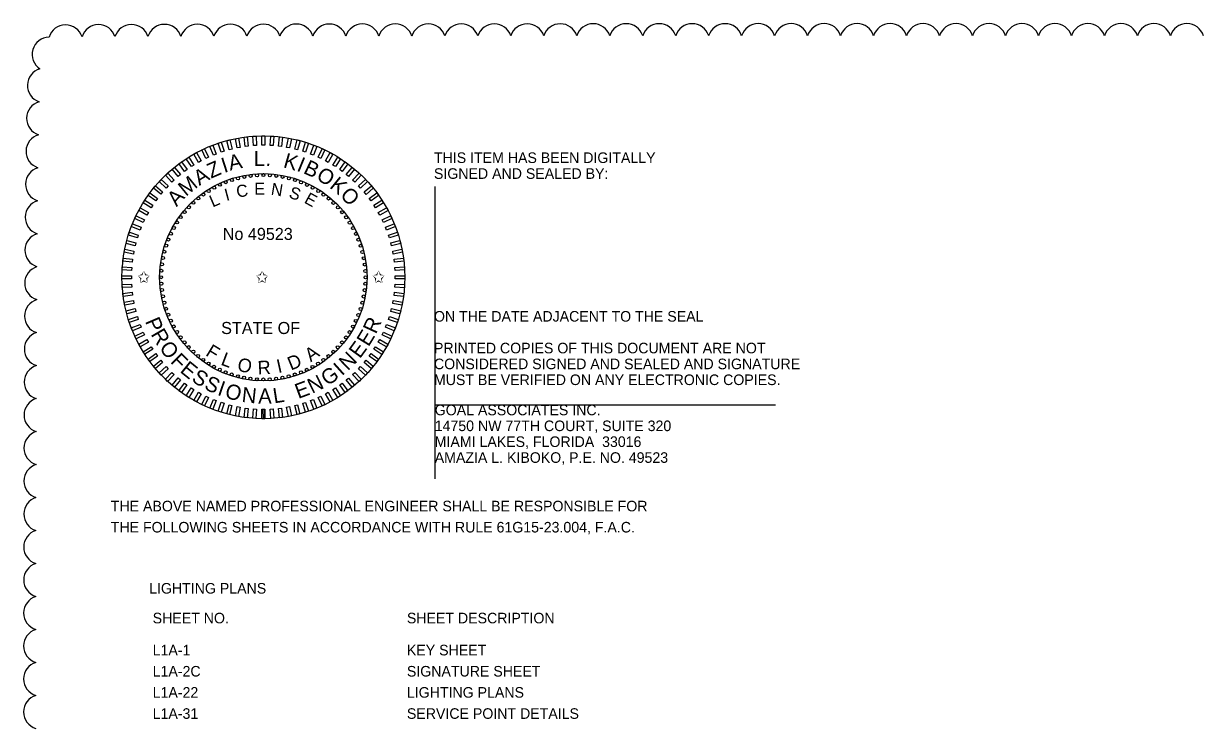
# Model space of a CAD drawing. Extents: x -811.2 to -795.1, y -2238.2 to -2204.
# Drawn here: x -811.08 to -803.27, y -2220.54 to -2215.88 of the extents above; entities that cross this region are included whole.
import ezdxf

# ---------------------------------------------------------------- set-up
doc = ezdxf.new("R2010")
doc.units = 0
for name, color, linetype in [('AdhocPoint_dp', 7, 'Continuous'), ('Cloud_dp', 7, 'Continuous'), ('PlotBorder_dp', 7, 'Continuous'), ('TextMinor', 7, 'Continuous'), ('TextMisc', 7, 'Continuous'), ('TextShtNo', 7, 'Continuous')]:
    doc.layers.add(name, color=color, linetype=linetype)

msp = doc.modelspace()

# ---------------------------------------------------------------- linework, layer by layer
at = {"layer": 'AdhocPoint_dp'}
for p, q in [((-808.3546, -2216.9552), (-808.3546, -2218.8899)), ((-808.3546, -2218.3999), (-806.0979, -2218.3999))]:
    msp.add_line(p, q, dxfattribs=at)
at = {"layer": 'Cloud_dp'}
for centre, radius, start, end in [((-810.7982, -2216.0002), 0.1145, 18.05658, 163.05658), ((-810.58, -2215.9986), 0.1145, 17.79982, 162.79982), ((-810.3617, -2215.9976), 0.1145, 17.71875, 162.71875), ((-810.1434, -2215.9968), 0.1145, 17.67426, 162.67426), ((-809.9251, -2215.9962), 0.1145, 17.64508, 162.64508), ((-809.7068, -2215.9957), 0.1145, 17.62402, 162.62402), ((-809.4885, -2215.9953), 0.1145, 17.60791, 162.60791), ((-809.2702, -2215.9949), 0.1145, 17.59506, 162.59506), ((-809.0518, -2215.9946), 0.1145, 17.5845, 162.5845), ((-808.8335, -2215.9943), 0.1145, 17.57563, 162.57563), ((-808.6152, -2215.994), 0.1145, 17.56803, 162.56803), ((-808.3969, -2215.9937), 0.1145, 17.56143, 162.56143), ((-808.1786, -2215.9935), 0.1145, 17.55563, 162.55563), ((-807.9602, -2215.9933), 0.1145, 17.55047, 162.55047), ((-807.7419, -2215.9931), 0.1145, 17.54585, 162.54585), ((-807.5236, -2215.993), 0.1145, 17.54168, 162.54168), ((-807.3053, -2215.9928), 0.1145, 17.53789, 162.53789), ((-807.087, -2215.9927), 0.1145, 17.53443, 162.53443), ((-806.8686, -2215.9925), 0.1145, 17.53125, 162.53125), ((-806.6503, -2215.9924), 0.1145, 17.52832, 162.52832), ((-806.432, -2215.9923), 0.1145, 17.52559, 162.52559), ((-806.2137, -2215.9922), 0.1145, 17.52306, 162.52306), ((-805.9953, -2215.9922), 0.1145, 17.5207, 162.5207), ((-805.777, -2215.9921), 0.1145, 17.51849, 162.51849), ((-805.5587, -2215.992), 0.1145, 17.51642, 162.51642), ((-805.3404, -2215.992), 0.1145, 17.51447, 162.51447), ((-805.1221, -2215.9919), 0.1145, 17.51263, 162.51263), ((-804.9037, -2215.9919), 0.1145, 17.51089, 162.51089), ((-804.6854, -2215.9918), 0.1145, 17.50924, 162.50924), ((-804.4671, -2215.9918), 0.1145, 17.50767, 162.50767), ((-804.2488, -2215.9918), 0.1145, 17.50619, 162.50619), ((-804.0304, -2215.9917), 0.1145, 17.50477, 162.50477), ((-803.8121, -2215.9917), 0.1145, 17.50342, 162.50342), ((-803.5938, -2215.9917), 0.1145, 17.50213, 162.50213), ((-803.3755, -2215.9917), 0.1145, 17.5009, 162.5009), ((-810.9047, -2216.0812), 0.1144, 91.47713, 236.47713), ((-810.9365, -2216.2866), 0.1145, 105.90805, 250.90805), ((-810.9416, -2216.5046), 0.1145, 106.41676, 251.41676), ((-810.9452, -2216.7227), 0.1145, 106.67623, 251.67623), ((-810.9481, -2216.9409), 0.1145, 106.84098, 251.84098), ((-810.9504, -2217.1592), 0.1145, 106.95758, 251.95758), ((-810.9523, -2217.3774), 0.1145, 107.04572, 252.04572), ((-810.9539, -2217.5957), 0.1145, 107.11538, 252.11538), ((-810.9552, -2217.814), 0.1145, 107.17224, 252.17224), ((-810.9564, -2218.0323), 0.1145, 107.21979, 252.21979), ((-810.9574, -2218.2506), 0.1145, 107.26033, 252.26033), ((-810.9582, -2218.4689), 0.1145, 107.29543, 252.29543), ((-810.9589, -2218.6872), 0.1145, 107.3262, 252.3262), ((-810.9595, -2218.9055), 0.1145, 107.35348, 252.35348), ((-810.9601, -2219.1238), 0.1145, 107.37786, 252.37786), ((-810.9605, -2219.3421), 0.1145, 107.39984, 252.39984), ((-810.9608, -2219.5604), 0.1145, 107.41978, 252.41978), ((-810.9611, -2219.7788), 0.1145, 107.43798, 252.43798), ((-810.9613, -2219.9971), 0.1145, 107.45468, 252.45468), ((-810.9614, -2220.2154), 0.1145, 107.47007, 252.47007), ((-810.9615, -2220.4337), 0.1145, 107.48432, 252.48432)]:
    msp.add_arc(centre, radius, start, end, dxfattribs=at)
at = {"layer": 'TextMinor'}
for radius in [0.9361, 0.6864]:
    msp.add_circle((-809.4889, -2217.5565), radius, dxfattribs=at)
at = {"layer": 'TextShtNo'}
for p, q in [((-809.4989, -2218.4926), (-809.4991, -2218.4302)), ((-809.4889, -2218.4926), (-809.4891, -2218.4302)), ((-809.479, -2218.4926), (-809.4791, -2218.4302))]:
    msp.add_line(p, q, dxfattribs=at)
for points in [[(-809.8011, -2216.7405), (-809.8198, -2216.7479), (-809.8428, -2216.6899), (-809.8241, -2216.6825)], [(-809.7493, -2216.7225), (-809.7684, -2216.7287), (-809.7877, -2216.6694), (-809.7685, -2216.6632)], [(-809.6964, -2216.7078), (-809.7159, -2216.7128), (-809.7314, -2216.6524), (-809.7119, -2216.6474)], [(-809.6427, -2216.6964), (-809.6625, -2216.7002), (-809.6741, -2216.639), (-809.6543, -2216.6352)], [(-809.5884, -2216.6885), (-809.6083, -2216.691), (-809.6162, -2216.6291), (-809.5962, -2216.6266)], [(-809.5336, -2216.6839), (-809.5538, -2216.6852), (-809.5577, -2216.623), (-809.5376, -2216.6217)], [(-809.4788, -2216.6829), (-809.4989, -2216.6829), (-809.4989, -2216.6205), (-809.4788, -2216.6205)], [(-809.4239, -2216.6852), (-809.444, -2216.684), (-809.4401, -2216.6217), (-809.42, -2216.623)], [(-809.3693, -2216.691), (-809.3893, -2216.6885), (-809.3815, -2216.6266), (-809.3615, -2216.6292)], [(-809.3152, -2216.7002), (-809.335, -2216.6965), (-809.3234, -2216.6352), (-809.3036, -2216.639)], [(-809.2618, -2216.7128), (-809.2813, -2216.7078), (-809.2658, -2216.6474), (-809.2463, -2216.6525)], [(-809.2093, -2216.7288), (-809.2285, -2216.7225), (-809.2092, -2216.6632), (-809.19, -2216.6695)], [(-809.1579, -2216.748), (-809.1766, -2216.7405), (-809.1537, -2216.6826), (-809.1349, -2216.69)], [(-809.9485, -2216.8134), (-809.9655, -2216.8242), (-809.9989, -2216.7716), (-809.9819, -2216.7608)], [(-809.9009, -2216.786), (-809.9186, -2216.7957), (-809.9486, -2216.7411), (-809.931, -2216.7314)], [(-809.8517, -2216.7617), (-809.87, -2216.7703), (-809.8965, -2216.7139), (-809.8783, -2216.7053)], [(-809.1077, -2216.7703), (-809.126, -2216.7618), (-809.0994, -2216.7053), (-809.0812, -2216.7139)], [(-809.0591, -2216.7958), (-809.0768, -2216.7861), (-809.0468, -2216.7315), (-809.0291, -2216.7412)], [(-809.0122, -2216.8243), (-809.0292, -2216.8135), (-808.9958, -2216.7609), (-808.9788, -2216.7717)], [(-810.038, -2216.8769), (-810.0535, -2216.8897), (-810.0933, -2216.8417), (-810.0777, -2216.8288)], [(-809.9943, -2216.8437), (-810.0106, -2216.8556), (-810.0472, -2216.8051), (-810.0309, -2216.7933)], [(-808.9672, -2216.8557), (-808.9835, -2216.8438), (-808.9468, -2216.7934), (-808.9305, -2216.8053)], [(-808.9242, -2216.8898), (-808.9397, -2216.877), (-808.9, -2216.829), (-808.8845, -2216.8418)], [(-810.1189, -2216.9511), (-810.1327, -2216.9657), (-810.1781, -2216.9231), (-810.1643, -2216.9084)], [(-810.0796, -2216.9127), (-810.0943, -2216.9265), (-810.137, -2216.881), (-810.1223, -2216.8672)], [(-808.8835, -2216.9266), (-808.8981, -2216.9128), (-808.8555, -2216.8674), (-808.8408, -2216.8812)], [(-808.8451, -2216.9659), (-808.8589, -2216.9512), (-808.8134, -2216.9085), (-808.7996, -2216.9232)], [(-810.1898, -2217.0348), (-810.2016, -2217.0511), (-810.2521, -2217.0144), (-810.2402, -2216.9981)], [(-810.1556, -2216.9918), (-810.1685, -2217.0073), (-810.2165, -2216.9676), (-810.2037, -2216.9521)], [(-808.8093, -2217.0075), (-808.8221, -2216.9919), (-808.7741, -2216.9522), (-808.7612, -2216.9677)], [(-808.7761, -2217.0512), (-808.788, -2217.0349), (-808.7375, -2216.9983), (-808.7257, -2217.0146)], [(-810.2212, -2217.0798), (-810.232, -2217.0968), (-810.2846, -2217.0634), (-810.2738, -2217.0464)], [(-808.7458, -2217.097), (-808.7566, -2217.08), (-808.704, -2217.0466), (-808.6932, -2217.0636)], [(-810.2751, -2217.1753), (-810.2837, -2217.1936), (-810.3401, -2217.167), (-810.3316, -2217.1488)], [(-810.2497, -2217.1267), (-810.2594, -2217.1444), (-810.314, -2217.1144), (-810.3043, -2217.0967)], [(-808.7184, -2217.1446), (-808.7281, -2217.1269), (-808.6735, -2217.0969), (-808.6638, -2217.1145)], [(-808.6941, -2217.1937), (-808.7027, -2217.1755), (-808.6463, -2217.149), (-808.6377, -2217.1672)], [(-810.2975, -2217.2255), (-810.3049, -2217.2442), (-810.3629, -2217.2213), (-810.3555, -2217.2025)], [(-808.6729, -2217.2444), (-808.6803, -2217.2256), (-808.6223, -2217.2027), (-808.6149, -2217.2214)], [(-810.3326, -2217.3294), (-810.3377, -2217.3489), (-810.398, -2217.3334), (-810.393, -2217.3139)], [(-810.3167, -2217.2769), (-810.3229, -2217.2961), (-810.3822, -2217.2768), (-810.376, -2217.2576)], [(-808.6549, -2217.2962), (-808.6611, -2217.2771), (-808.6018, -2217.2578), (-808.5956, -2217.277)], [(-808.6402, -2217.3491), (-808.6452, -2217.3296), (-808.5848, -2217.3141), (-808.5798, -2217.3336)], [(-810.3452, -2217.3828), (-810.349, -2217.4026), (-810.4103, -2217.391), (-810.4065, -2217.3712)], [(-808.6288, -2217.4028), (-808.6326, -2217.383), (-808.5714, -2217.3713), (-808.5676, -2217.3911)], [(-810.3545, -2217.4369), (-810.357, -2217.4569), (-810.4188, -2217.4491), (-810.4163, -2217.4291)], [(-808.6209, -2217.4571), (-808.6234, -2217.4371), (-808.5615, -2217.4293), (-808.559, -2217.4493)], [(-810.3626, -2217.5464), (-810.3626, -2217.5665), (-810.425, -2217.5665), (-810.425, -2217.5464)], [(-810.3603, -2217.4915), (-810.3615, -2217.5116), (-810.4237, -2217.5077), (-810.4225, -2217.4876)], [(-808.6163, -2217.5118), (-808.6176, -2217.4917), (-808.5554, -2217.4878), (-808.5541, -2217.5079)], [(-808.6153, -2217.5667), (-808.6153, -2217.5466), (-808.5529, -2217.5466), (-808.5529, -2217.5667)], [(-810.3615, -2217.6012), (-810.3603, -2217.6214), (-810.4225, -2217.6253), (-810.4238, -2217.6052)], [(-808.6176, -2217.6216), (-808.6164, -2217.6014), (-808.5541, -2217.6053), (-808.5554, -2217.6255)], [(-810.357, -2217.656), (-810.3545, -2217.6759), (-810.4163, -2217.6838), (-810.4189, -2217.6638)], [(-810.3491, -2217.7103), (-810.3453, -2217.7301), (-810.4065, -2217.7417), (-810.4103, -2217.7219)], [(-808.6326, -2217.7302), (-808.6289, -2217.7104), (-808.5676, -2217.7221), (-808.5714, -2217.7419)], [(-808.6234, -2217.6761), (-808.6209, -2217.6561), (-808.559, -2217.664), (-808.5616, -2217.6839)], [(-810.3377, -2217.764), (-810.3327, -2217.7835), (-810.3931, -2217.799), (-810.3981, -2217.7795)], [(-808.6452, -2217.7837), (-808.6402, -2217.7641), (-808.5798, -2217.7796), (-808.5849, -2217.7992)], [(-810.323, -2217.8169), (-810.3168, -2217.836), (-810.3761, -2217.8553), (-810.3823, -2217.8361)], [(-810.305, -2217.8687), (-810.2976, -2217.8874), (-810.3556, -2217.9104), (-810.363, -2217.8917)], [(-808.6612, -2217.8362), (-808.6549, -2217.817), (-808.5956, -2217.8363), (-808.6019, -2217.8555)], [(-810.2838, -2217.9193), (-810.2752, -2217.9376), (-810.3316, -2217.9641), (-810.3402, -2217.9459)], [(-808.7027, -2217.9377), (-808.6942, -2217.9195), (-808.6377, -2217.946), (-808.6463, -2217.9643)], [(-808.6804, -2217.8876), (-808.6729, -2217.8689), (-808.615, -2217.8918), (-808.6224, -2217.9106)], [(-810.2595, -2217.9685), (-810.2497, -2217.9862), (-810.3044, -2218.0162), (-810.3141, -2217.9986)], [(-810.2321, -2218.0161), (-810.2213, -2218.0331), (-810.2739, -2218.0665), (-810.2847, -2218.0495)], [(-808.7567, -2218.0333), (-808.7459, -2218.0163), (-808.6933, -2218.0497), (-808.7041, -2218.0667)], [(-808.7282, -2217.9864), (-808.7185, -2217.9687), (-808.6639, -2217.9987), (-808.6736, -2218.0164)], [(-810.2017, -2218.0618), (-810.1899, -2218.0782), (-810.2403, -2218.1148), (-810.2522, -2218.0985)], [(-808.7881, -2218.0783), (-808.7762, -2218.062), (-808.7258, -2218.0986), (-808.7377, -2218.115)], [(-810.1686, -2218.1056), (-810.1558, -2218.1211), (-810.2038, -2218.1609), (-810.2166, -2218.1453)], [(-810.1328, -2218.1472), (-810.119, -2218.1619), (-810.1644, -2218.2046), (-810.1782, -2218.1899)], [(-808.859, -2218.162), (-808.8452, -2218.1473), (-808.7998, -2218.19), (-808.8136, -2218.2047)], [(-808.8222, -2218.1213), (-808.8094, -2218.1058), (-808.7614, -2218.1455), (-808.7742, -2218.161)], [(-810.0944, -2218.1865), (-810.0797, -2218.2003), (-810.1224, -2218.2457), (-810.1371, -2218.2319)], [(-810.0537, -2218.2232), (-810.0382, -2218.2361), (-810.0779, -2218.2841), (-810.0934, -2218.2713)], [(-810.0107, -2218.2574), (-809.9944, -2218.2692), (-810.031, -2218.3197), (-810.0474, -2218.3078)], [(-808.9836, -2218.2693), (-808.9673, -2218.2575), (-808.9307, -2218.3079), (-808.947, -2218.3198)], [(-808.9399, -2218.2362), (-808.9243, -2218.2234), (-808.8846, -2218.2714), (-808.9001, -2218.2842)], [(-808.8983, -2218.2004), (-808.8836, -2218.1866), (-808.8409, -2218.232), (-808.8556, -2218.2458)], [(-809.9657, -2218.2888), (-809.9487, -2218.2996), (-809.9821, -2218.3522), (-809.9991, -2218.3414)], [(-809.9188, -2218.3173), (-809.9011, -2218.327), (-809.9311, -2218.3816), (-809.9488, -2218.3719)], [(-809.077, -2218.3271), (-809.0593, -2218.3173), (-809.0293, -2218.372), (-809.0469, -2218.3817)], [(-809.0294, -2218.2997), (-809.0124, -2218.2889), (-808.979, -2218.3415), (-808.996, -2218.3523)], [(-809.8701, -2218.3427), (-809.8519, -2218.3513), (-809.8784, -2218.4077), (-809.8967, -2218.3992)], [(-809.82, -2218.3651), (-809.8013, -2218.3725), (-809.8242, -2218.4305), (-809.843, -2218.4231)], [(-809.7686, -2218.3843), (-809.7494, -2218.3905), (-809.7687, -2218.4498), (-809.7879, -2218.4436)], [(-809.7161, -2218.4002), (-809.6965, -2218.4053), (-809.7121, -2218.4656), (-809.7316, -2218.4606)], [(-809.6626, -2218.4128), (-809.6428, -2218.4166), (-809.6545, -2218.4779), (-809.6743, -2218.4741)], [(-809.3352, -2218.4167), (-809.3154, -2218.4129), (-809.3037, -2218.4741), (-809.3235, -2218.4779)], [(-809.2815, -2218.4053), (-809.262, -2218.4003), (-809.2465, -2218.4607), (-809.266, -2218.4657)], [(-809.2286, -2218.3906), (-809.2095, -2218.3844), (-809.1902, -2218.4437), (-809.2094, -2218.4499)], [(-809.1768, -2218.3726), (-809.158, -2218.3652), (-809.1351, -2218.4232), (-809.1538, -2218.4306)], [(-809.1261, -2218.3514), (-809.1079, -2218.3428), (-809.0814, -2218.3992), (-809.0996, -2218.4078)], [(-809.6085, -2218.4221), (-809.5885, -2218.4246), (-809.5964, -2218.4864), (-809.6163, -2218.4839)], [(-809.554, -2218.4279), (-809.5338, -2218.4291), (-809.5377, -2218.4913), (-809.5579, -2218.4901)], [(-809.4991, -2218.4302), (-809.479, -2218.4302), (-809.479, -2218.4926), (-809.4991, -2218.4926)], [(-809.4442, -2218.4291), (-809.4241, -2218.4279), (-809.4202, -2218.4901), (-809.4403, -2218.4914)], [(-809.3895, -2218.4246), (-809.3695, -2218.4221), (-809.3617, -2218.4839), (-809.3817, -2218.4865)]]:
    msp.add_lwpolyline(points, close=True, dxfattribs=at)
for centre in [(-809.7374, -2216.9274), (-809.6974, -2216.913), (-809.6566, -2216.9012), (-809.6151, -2216.892), (-809.5732, -2216.8854), (-809.5309, -2216.8814), (-809.4884, -2216.8801), (-809.4459, -2216.8815), (-809.4036, -2216.8855), (-809.3616, -2216.8922), (-809.3202, -2216.9015), (-809.2794, -2216.9134), (-809.2394, -2216.9278), (-809.8861, -2217.009), (-809.8509, -2216.9851), (-809.8143, -2216.9635), (-809.7764, -2216.9443), (-809.2004, -2216.9447), (-809.1626, -2216.9641), (-809.126, -2216.9857), (-809.0909, -2217.0096), (-809.9816, -2217.0931), (-809.9516, -2217.0631), (-809.9197, -2217.035), (-809.0573, -2217.0357), (-809.0255, -2217.0638), (-808.9955, -2217.0939), (-810.0358, -2217.1585), (-810.0098, -2217.1249), (-808.9674, -2217.1258), (-808.9414, -2217.1594), (-810.0814, -2217.2302), (-810.0598, -2217.1936), (-808.9175, -2217.1946), (-808.8959, -2217.2312), (-810.1177, -2217.307), (-810.1007, -2217.268), (-808.8767, -2217.269), (-808.8598, -2217.3081), (-810.144, -2217.3878), (-810.1321, -2217.347), (-808.8454, -2217.348), (-808.8336, -2217.3889), (-810.16, -2217.4712), (-810.1533, -2217.4292), (-808.8244, -2217.4303), (-808.8178, -2217.4723), (-810.1654, -2217.556), (-810.164, -2217.5135), (-808.8138, -2217.5146), (-808.8125, -2217.5571), (-810.1641, -2217.5985), (-810.1601, -2217.6408), (-808.8179, -2217.6419), (-808.8139, -2217.5996), (-810.1535, -2217.6827), (-808.8246, -2217.6838), (-810.1443, -2217.7242), (-810.1324, -2217.765), (-808.8458, -2217.7661), (-808.8339, -2217.7253), (-810.1181, -2217.805), (-810.1012, -2217.844), (-808.8771, -2217.8451), (-808.8602, -2217.8061), (-810.082, -2217.8819), (-810.0604, -2217.9185), (-810.0365, -2217.9537), (-808.942, -2217.9546), (-808.9181, -2217.9195), (-808.8965, -2217.8829), (-810.0105, -2217.9873), (-809.9824, -2218.0192), (-808.9962, -2218.02), (-808.9681, -2217.9881), (-809.9524, -2218.0492), (-809.9205, -2218.0774), (-809.887, -2218.1034), (-809.0918, -2218.1041), (-809.0582, -2218.0781), (-809.0263, -2218.05), (-809.8519, -2218.1274), (-809.8153, -2218.149), (-809.7775, -2218.1683), (-809.7385, -2218.1853), (-809.2405, -2218.1857), (-809.2014, -2218.1688), (-809.1636, -2218.1496), (-809.127, -2218.128), (-809.6985, -2218.1997), (-809.6577, -2218.2116), (-809.6162, -2218.2209), (-809.5743, -2218.2276), (-809.532, -2218.2316), (-809.4889, -2218.233), (-809.447, -2218.2317), (-809.4047, -2218.2277), (-809.3627, -2218.2211), (-809.3213, -2218.2119), (-809.2805, -2218.2)]:
    msp.add_circle(centre, 0.00998, dxfattribs=at)

# ---------------------------------------------------------------- texts
at = {"layer": 'PlotBorder_dp'}
for s, height, rotation, p in [('I', 0.0998, 17.68363, (-809.7486, -2216.8667)), ('A', 0.0998, 11.91844, (-809.7094, -2216.8507)), ('L', 0.0998, 359.96623, (-809.5524, -2216.8204)), ('K', 0.0998, 344.27273, (-809.3621, -2216.8275)), ('I', 0.0998, 337.77772, (-809.2736, -2216.8494)), ('A', 0.0998, 31.46601, (-809.9127, -2216.9527)), ('Z', 0.0998, 23.30524, (-809.8354, -2216.9042)), ('.', 0.0998, 353.78581, (-809.4759, -2216.8175)), ('B', 0.0998, 334.48695, (-809.2297, -2216.8647)), ('O', 0.0998, 327.82385, (-809.1452, -2216.9032)), ('M', 0.0998, 39.30005, (-810.0016, -2217.0248)), ('K', 0.0998, 321.0594, (-809.0557, -2216.9603)), ('A', 0.0998, 46.80938, (-810.0637, -2217.0931)), ('O', 0.0998, 314.20329, (-808.9862, -2217.0178)), ('P', 0.0999, 293.19548, (-810.2734, -2217.8476)), ('R', 0.0999, 65.28865, (-808.7437, -2217.9369)), ('R', 0.0999, 300.25949, (-810.2366, -2217.9335)), ('E', 0.0999, 58.61694, (-808.7928, -2218.0207)), ('O', 0.0999, 307.26617, (-810.1825, -2218.0251)), ('F', 0.0899, 328.53399, (-809.8768, -2218.0711)), ('A', 0.0899, 35.54629, (-809.175, -2218.1203)), ('E', 0.0999, 53.99864, (-808.85, -2218.0993)), ('F', 0.0999, 314.20329, (-810.1092, -2218.1175)), ('L', 0.0899, 339.48752, (-809.7757, -2218.1339)), ('O', 0.0899, 348.08156, (-809.6664, -2218.1745)), ('I', 0.0899, 12.52485, (-809.3905, -2218.1915)), ('D', 0.0899, 22.22228, (-809.3065, -2218.1747)), ('N', 0.0999, 44.34211, (-808.9299, -2218.1791)), ('E', 0.0999, 321.0594, (-810.046, -2218.1809)), ('S', 0.0999, 327.82385, (-809.9699, -2218.2414)), ('R', 0.0899, 3.10738, (-809.5245, -2218.2007)), ('G', 0.0999, 34.11362, (-809.0652, -2218.2791)), ('I', 0.0999, 41.83906, (-808.9692, -2218.2133)), ('S', 0.0999, 334.48695, (-809.8869, -2218.2927)), ('I', 0.0999, 341.03996, (-809.7985, -2218.334)), ('E', 0.0999, 20.51248, (-809.2576, -2218.3625)), ('N', 0.0999, 26.0618, (-809.1662, -2218.3292)), ('O', 0.0999, 344.27273, (-809.7494, -2218.3515)), ('N', 0.0999, 353.78581, (-809.6352, -2218.3814)), ('A', 0.0999, 359.96623, (-809.523, -2218.3924)), ('L', 0.0999, 8.98261, (-809.4176, -2218.3915))]:
    msp.add_text(s, height=height, rotation=rotation, dxfattribs=at).set_placement(p)
for s, height, p in [('THIS ITEM HAS BEEN DIGITALLY', 0.07, (-808.3596, -2216.8)), ('SIGNED AND SEALED BY:', 0.07, (-808.3596, -2216.905)), ('No 49523', 0.07988, (-809.7575, -2217.3097)), ('ON THE DATE ADJACENT TO THE SEAL', 0.07, (-808.3596, -2217.85)), ('STATE OF', 0.07988, (-809.7682, -2217.9322)), ('PRINTED COPIES OF THIS DOCUMENT ARE NOT ', 0.07, (-808.3596, -2218.06)), ('CONSIDERED SIGNED AND SEALED AND SIGNATURE ', 0.07, (-808.3596, -2218.165)), ('MUST BE VERIFIED ON ANY ELECTRONIC COPIES.', 0.07, (-808.3596, -2218.27)), ('GOAL ASSOCIATES INC.', 0.07, (-808.3546, -2218.4699)), ('14750 NW 77TH COURT, SUITE 320', 0.07, (-808.3546, -2218.5749)), ('MIAMI LAKES, FLORIDA  33016', 0.07, (-808.3546, -2218.6799)), ('AMAZIA L. KIBOKO, P.E. NO. 49523', 0.07, (-808.3546, -2218.7849)), ('THE ABOVE NAMED PROFESSIONAL ENGINEER SHALL BE RESPONSIBLE FOR ', 0.07, (-810.4987, -2219.106)), ('THE FOLLOWING SHEETS IN ACCORDANCE WITH RULE 61G15-23.004, F.A.C.', 0.07, (-810.4987, -2219.246)), ('LIGHTING PLANS', 0.07, (-810.245, -2219.6504))]:
    msp.add_text(s, height=height, dxfattribs=at).set_placement(p)
at = {"layer": 'TextMisc'}
for s, p in [('SHEET NO.', (-810.2215, -2219.8474)), ('SHEET DESCRIPTION', (-808.5387, -2219.8474)), ('L1A-1', (-810.2215, -2220.0595)), ('KEY SHEET', (-808.5387, -2220.0595)), ('L1A-2C', (-810.2215, -2220.1995)), ('SIGNATURE SHEET', (-808.5387, -2220.1995)), ('L1A-22', (-810.2215, -2220.3395)), ('LIGHTING PLANS', (-808.5387, -2220.3395)), ('L1A-31 ', (-810.2215, -2220.4795)), ('SERVICE POINT DETAILS', (-808.5387, -2220.4795))]:
    msp.add_text(s, height=0.07, dxfattribs=at).set_placement(p)
at = {"layer": 'TextShtNo'}
for s, rotation, p in [('E', 359.96623, (-809.5491, -2217.0106)), ('I', 14.81888, (-809.7341, -2217.0521)), ('C', 8.98261, (-809.6617, -2217.0295)), ('N', 350.64643, (-809.4424, -2217.0092)), ('S', 341.03996, (-809.3254, -2217.0279)), ('E', 331.16864, (-809.2242, -2217.0605)), ('L', 23.30524, (-809.8246, -2217.0949))]:
    msp.add_text(s, height=0.0799, rotation=rotation, dxfattribs=at).set_placement(p)
for p in [(-810.3226, -2217.5944), (-809.5391, -2217.5944), (-808.7685, -2217.5944)]:
    msp.add_text('✩', height=0.0799, dxfattribs=at).set_placement(p)

doc.saveas('drawing.dxf')
